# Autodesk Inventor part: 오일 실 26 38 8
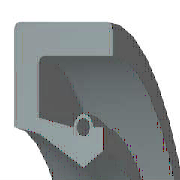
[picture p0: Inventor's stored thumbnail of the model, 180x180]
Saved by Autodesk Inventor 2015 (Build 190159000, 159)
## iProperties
IsCustomPart: 1
Created: 2012-02
Part Number: 오일 실 26 38 8
Material: 고무
Description: 오일-실
Document SubType Name: Modeling
Standard: KS B 2804
Designer: mduedu
Standards Organization: KS
Language: ko-KR
Size Designation: S - 26 38 8
Categories: <MemberInstance><Categories><Category DisplayName="샤프트 부품" InternalName="7f7aeb1f-a693-4053-b835-cee3144e0d98" Mnemonic="SHFT"><Category DisplayName="실링" Intern
Density: 0.93 g/cm^3
Appearance: 고무 - 검은색 - 버전 1.1
Author: mduedu
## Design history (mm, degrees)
revolve "본체" stored, may be unused: angle "d17" = 90 deg
revolve "스프링1" stored, may be unused: angle "d18" = 90 deg
body "Solid1"
sketch "스케치1"
  geometry: L1 (0, 19)-(8, 19); L2 (8, 19)-(8, 17.75); L3 (8, 17.75)-(1.75, 17.75); L4 (0, 19)-(0, 15.1); L5 (0, 15.1)-(1.75, 14.75); L6 (1.75, 14.75)-(4.9, 13); L7 (4.9, 13)-(0, 13); L8 (6.3, 13.875)-(6.3, 15.1); L9 (0, 0)-(9.586, 0) reference; L10 (4.9, 13)-(6.3, 13.875); L11 (0, 18)-(0, -3) reference; L12 (-1.917, 0)-(11.503, 0) reference; L13 (4.2, 15.1)-(1.75, 15.59); L14 (1.75, 15.59)-(1.75, 17.75); L15 (6.3, 15.1)-(5.6, 15.1); C1 r 0.455 at (4.9, 15.1); A1 r 0.7 centre (4.9, 15.1) between (5.6, 15.1) and (4.2, 15.1)
  constraints: 26 end point, 5 horizontal alignment, 4 perpendicular, 2 centre point, 2 collinear, 2 horizontal, 2 parallel, 2 point on circle, 2 point on line, 2 vertical alignment, 1 coincident
  dimensions: "d0" = 38 diameter of L1 L9 (= SD2); "d1" = 27.75 diameter of L8.start L9 (= ABDM); "d2" = 1.25 distance of L1.end L2.end (computed from SD); "d3" = 0.91 diameter of C1 (= SPDI); "d4" = 1.4 diameter of A1 (= SPDA); "d5" = 26 diameter of L6.end L9 (= NND); "d6" = 29.5 diameter of L5.end L9 (= TKDM); "d7" = 30.2 diameter of L4.end L9 (= HLDM); "d8" = 4.9 distance from line of C1.centre L4 (= SPDST); "d9" = 6.3 distance between parallel lines of L8 L4 (= SDI); "d10" = 8 distance between parallel lines of L2 L4 (= SWDT); "d12" = 1.75 distance between parallel lines of L14 L4 (= SD)
fillet "모깎기1" dims "d11" = 0.3 (= RR)
other parameters: "SD2" = 38 [user parameter; used in 1 equation term], "SWDT" = 8 [user parameter; used in 1 equation term], "RR" = 0.3 [user parameter; used in 1 equation term], "SD" = 1.75 [user parameter; used in 2 equation terms], "NND" = 26 [user parameter; used in 1 equation term], "SPDA" = 1.4 [user parameter; used in 1 equation term], "SPDI" = 0.91 [user parameter; used in 1 equation term], "TKDM" = 29.5 [user parameter; used in 1 equation term], "HLDM" = 30.2 [user parameter; used in 1 equation term], "ABDM" = 27.75 [user parameter; used in 1 equation term], "SDI" = 6.3 [user parameter; used in 1 equation term], "SPDST" = 4.9 [user parameter; used in 1 equation term], "d13" = 0, "d14" = 0, "d15" = 0, "LAB" = 0.35 [user parameter]
